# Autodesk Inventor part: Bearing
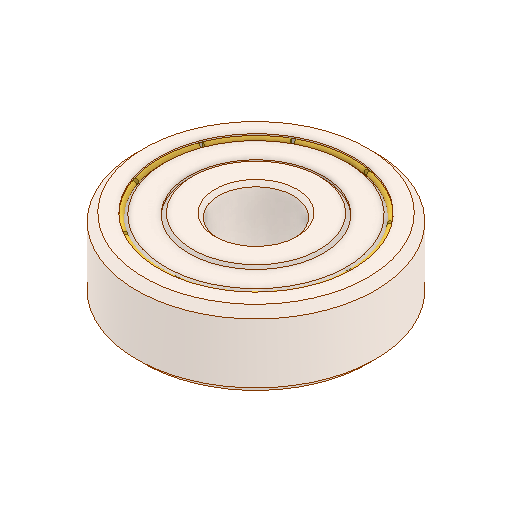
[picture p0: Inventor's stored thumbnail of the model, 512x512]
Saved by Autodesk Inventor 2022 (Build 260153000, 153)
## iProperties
Created: 2020-10
Part Number: Bearing
Material: Generico
Document SubType Name: Modeling
Designer: admin
Density: 1 g/cm^3
Appearance: Default
Author: admin
Sending System: SolidWorks 2020
Last Author: Simon
Last Saved: 2020-10-29
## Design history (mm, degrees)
feature "Revolve1"
feature "Revolve2"
feature "CirPattern1[1]" [Revolve]
feature "CirPattern1[2]" [Revolve]
feature "CirPattern1[3]" [Revolve]
feature "CirPattern1[4]" [Revolve]
feature "CirPattern1[5]" [Revolve]
feature "CirPattern1[6]" [Revolve]
feature "CirPattern1[7]" [Revolve]
feature "CirPattern1[8]" [Revolve]
feature "Mirror1[1]" [Revolve]
feature "Mirror1[2]" [Revolve]
feature "Mirror1[3]" [Revolve]
feature "Mirror1[4]" [Revolve]
feature "Mirror1[5]" [Revolve]
feature "Mirror1[6]" [Revolve]
feature "Mirror1[7]" [Revolve]
feature "Mirror1[8]" [Revolve]
feature "Mirror1[9]" [Revolve]
node "Solido1"
node "Solido2"
node "Solido3"
node "Solido4"
node "Solido5"
node "Solido6"
node "Solido7"
node "Solido8"
node "Solido9"
node "Solido10"
node "Solido11"
node "Solido12"
node "Solido13"
node "Solido14"
node "Solido15"
node "Solido16"
node "Solido17"
node "Solido18"
node "Solido19"
